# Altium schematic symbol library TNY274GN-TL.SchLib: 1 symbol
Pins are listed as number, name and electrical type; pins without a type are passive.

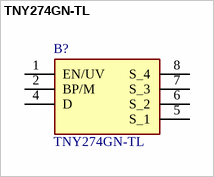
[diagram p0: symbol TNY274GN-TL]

## TNY274GN-TL
designator B?
AC/DC Converters 8.5W 85-265 VAC 11W/230 VAC; Manufacturer_Name: Power Integrations; Geometry.Height: 3.98mm
footprint TNY274GNTL
pins: 1 EN/UV, 2 BP/M, 4 D, 5 S_1, 6 S_2, 7 S_3, 8 S_4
